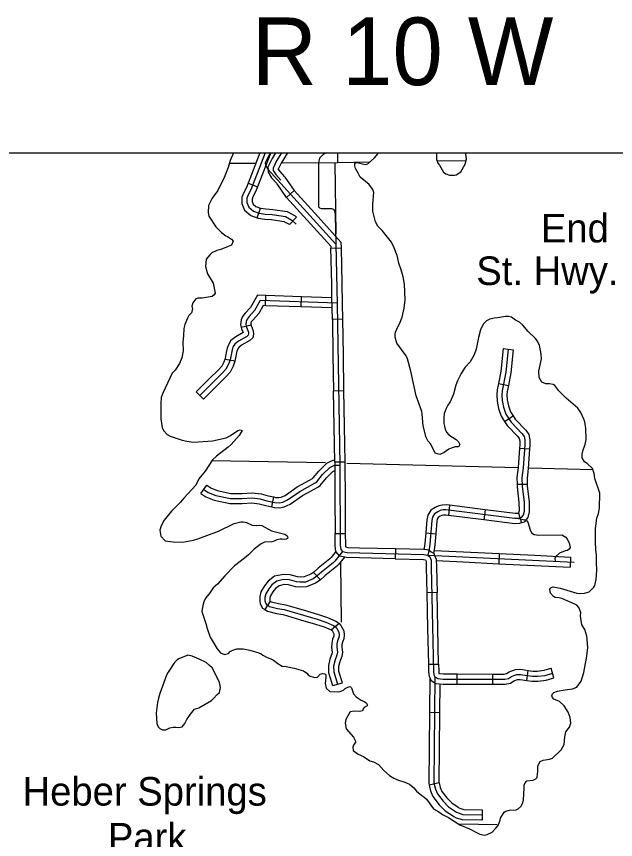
# Model space of a CAD drawing. Extents: x 1212896 to 1368412, y 378476 to 478763.
# Drawn here: x 1289419 to 1298275, y 427349 to 439519 of the extents above; entities that cross this region are included whole.
import ezdxf

# ---------------------------------------------------------------- set-up
doc = ezdxf.new("R2010")
doc.units = 0
for name, color, linetype in [('1', 7, 'Continuous'), ('Level 31', 7, 'Continuous'), ('Level 32', 7, 'Continuous'), ('Level 4', 7, 'Continuous'), ('Level 41', 7, 'Continuous'), ('Level 45', 7, 'Continuous'), ('Level 5', 7, 'Continuous'), ('Level 7', 7, 'Continuous'), ('Level 9', 7, 'Continuous'), ('R_Draft', 7, 'Continuous')]:
    doc.layers.add(name, color=color, linetype=linetype)

msp = doc.modelspace()

# ---------------------------------------------------------------- linework, layer by layer
at = {"layer": '1'}
msp.add_lwpolyline([(1257400, 437504), (1319317, 437504), (1319317, 388319), (1257400, 388319)], close=True, dxfattribs=at)
at = {"layer": 'Level 31'}
for p, q in [((1293175, 437493), (1293148, 437504)), ((1293288, 437261), (1293288, 437264)), ((1293524, 436945), (1293413, 436844)), ((1294067, 436095), (1294217, 436099)), ((1294086, 435209), (1294083, 435359)), ((1294239, 435043), (1294089, 435040)), ((1294106, 433984), (1294256, 433987)), ((1294274, 432931), (1294124, 432928)), ((1294130, 431873), (1294280, 431874)), ((1295020, 431651), (1295016, 431501)), ((1295636, 431000), (1295486, 430996)), ((1295508, 429941), (1295658, 429944))]:
    msp.add_line(p, q, dxfattribs=at)
for points in [[(1293248, 437504), (1293198, 437421), (1293137, 437292), (1293138, 437258)], [(1293181, 437504), (1293173, 437488)], [(1293424, 437504), (1293330, 437349), (1293288, 437261)], [(1293138, 437258), (1293139, 437216), (1293190, 437134), (1293270, 437047)], [(1293288, 437264), (1293288, 437261), (1293310, 437225), (1293381, 437147)], [(1293385, 437145), (1293524, 436945)], [(1293413, 436844), (1293273, 437043)], [(1293524, 436945), (1293879, 436554)], [(1293413, 436844), (1293768, 436453)], [(1293879, 436554), (1294216, 436182), (1294217, 436099)], [(1293768, 436453), (1294067, 436123), (1294067, 436095)], [(1294079, 435568), (1294067, 436095)], [(1294217, 436099), (1294229, 435571)], [(1294083, 435359), (1294079, 435568)], [(1294229, 435571), (1294235, 435270), (1294239, 435043)], [(1294089, 435040), (1294086, 435209)], [(1294089, 435040), (1294098, 434512)], [(1294239, 435043), (1294248, 434515)], [(1294098, 434512), (1294106, 433984)], [(1294248, 434515), (1294256, 433987)], [(1294115, 433456), (1294106, 433984)], [(1294256, 433987), (1294265, 433459)], [(1294124, 432928), (1294115, 433456)], [(1294265, 433459), (1294274, 432931)], [(1294124, 432928), (1294125, 432883), (1294127, 432401)], [(1294274, 432931), (1294275, 432884), (1294277, 432402)], [(1294127, 432401), (1294130, 431873)], [(1294277, 432402), (1294280, 431874)], [(1294488, 431514), (1294300, 431519), (1294201, 431541), (1294142, 431607), (1294131, 431698), (1294130, 431873)], [(1294280, 431874), (1294281, 431708), (1294285, 431676), (1294319, 431669), (1294492, 431664)], [(1294492, 431664), (1295020, 431651)], [(1295020, 431651), (1295443, 431641), (1295484, 431637), (1295521, 431627), (1295550, 431605), (1295583, 431583)], [(1295583, 431583), (1295593, 431570), (1295601, 431551)], [(1295601, 431551), (1295623, 431496), (1295628, 431378), (1295636, 431000)], [(1295016, 431501), (1294488, 431514)], [(1295016, 431501), (1295434, 431491), (1295466, 431486)], [(1295466, 431486), (1295475, 431464), (1295478, 431373), (1295486, 430996)], [(1295486, 430996), (1295497, 430469)], [(1295647, 430472), (1295636, 431000)], [(1295497, 430469), (1295508, 429941)], [(1295658, 429944), (1295647, 430472)]]:
    msp.add_lwpolyline(points, dxfattribs=at)
at = {"layer": 'Level 32'}
for p, q in [((1292844, 437056), (1292984, 437001)), ((1292977, 436543), (1293026, 436685)), ((1293456, 436441), (1293559, 436550)), ((1293101, 435242), (1293106, 435392)), ((1293628, 435224), (1293633, 435374)), ((1292887, 434957), (1292742, 434918)), ((1296615, 434608), (1296764, 434592)), ((1292650, 434421), (1292503, 434449)), ((1296544, 434091), (1296691, 434063)), ((1292184, 433862), (1292078, 433968)), ((1296636, 433532), (1296761, 433615)), ((1296855, 433134), (1297005, 433124)), ((1296819, 432602), (1296969, 432604)), ((1295823, 432291), (1295804, 432142)), ((1296347, 432224), (1296328, 432075)), ((1296839, 432174), (1296883, 432031)), ((1295469, 431883), (1295618, 431870)), ((1296963, 429702), (1296985, 429851)), ((1297364, 429739), (1297323, 429881)), ((1295934, 429647), (1295934, 429797)), ((1296462, 429646), (1296462, 429796))]:
    msp.add_line(p, q, dxfattribs=at)
for points in [[(1293098, 437504), (1292885, 436956), (1292845, 436884), (1292827, 436833), (1292826, 436767), (1292853, 436700), (1292921, 436640), (1293009, 436610), (1293097, 436597), (1293199, 436591), (1293395, 436560), (1293492, 436508), (1293555, 436449)], [(1293019, 437504), (1292844, 437056)], [(1293175, 437493), (1292984, 437001)], [(1293174, 437504), (1293149, 437464), (1293098, 437356), (1293099, 437319), (1293136, 437260), (1294140, 436152), (1294159, 435269), (1294198, 432884), (1294205, 431703), (1294213, 431639), (1294240, 431608), (1294309, 431593), (1295440, 431564), (1295498, 431556), (1295529, 431527), (1295548, 431480), (1295552, 431376), (1295584, 429837), (1295591, 429783), (1295606, 429754), (1295646, 429728), (1295729, 429721), (1296638, 429720), (1296693, 429731), (1296736, 429760), (1296811, 429788), (1296871, 429790), (1297046, 429764), (1297121, 429763), (1297235, 429777), (1297343, 429810)], [(1293338, 437504), (1293265, 437384), (1293214, 437276), (1293215, 437239), (1293251, 437181), (1293326, 437098)], [(1292844, 437056), (1292818, 436988), (1292778, 436915), (1292753, 436846), (1292752, 436753), (1292791, 436656), (1292883, 436575), (1292977, 436543)], [(1292984, 437001), (1292954, 436924), (1292915, 436853), (1292903, 436819), (1292902, 436781), (1292917, 436745), (1292960, 436707), (1293026, 436685)], [(1293026, 436685), (1293027, 436684), (1293104, 436674), (1293207, 436667), (1293420, 436633), (1293537, 436570), (1293559, 436550)], [(1292977, 436543), (1292991, 436538), (1293090, 436524), (1293191, 436518), (1293371, 436489), (1293449, 436448), (1293456, 436441)], [(1293024, 435318), (1292940, 435172), (1292859, 435082), (1292828, 435041), (1292813, 435011), (1292808, 434966), (1292819, 434926), (1292848, 434852), (1292850, 434828), (1292845, 434805), (1292826, 434789), (1292703, 434718), (1292648, 434675), (1292625, 434637), (1292606, 434591), (1292577, 434441), (1292555, 434376), (1292516, 434305), (1292464, 434248), (1292130, 433914)], [(1293106, 435392), (1292981, 435396), (1292878, 435217), (1292800, 435131), (1292762, 435081), (1292739, 435032), (1292731, 434960), (1292742, 434918)], [(1294159, 435280), (1293024, 435318)], [(1293633, 435374), (1293106, 435392)], [(1294083, 435359), (1293633, 435374)], [(1293101, 435242), (1293066, 435243), (1293000, 435128), (1292916, 435035), (1292891, 435003), (1292885, 434991), (1292883, 434971), (1292887, 434957)], [(1293628, 435224), (1293101, 435242)], [(1294086, 435209), (1293628, 435224)], [(1292887, 434957), (1292889, 434948), (1292920, 434870), (1292925, 434823), (1292911, 434765), (1292869, 434728), (1292745, 434657), (1292704, 434625), (1292691, 434604), (1292677, 434569), (1292667, 434520)], [(1292742, 434918), (1292746, 434902), (1292769, 434844), (1292661, 434781), (1292590, 434727), (1292557, 434672), (1292532, 434613), (1292520, 434548)], [(1296688, 434600), (1296651, 434260), (1296599, 433986), (1296592, 433925), (1296598, 433842), (1296618, 433741), (1296652, 433640), (1296733, 433518), (1296889, 433355), (1296922, 433308), (1296932, 433253), (1296932, 433184), (1296910, 432843), (1296892, 432698), (1296893, 432571), (1296922, 432337), (1296924, 432201), (1296911, 432146), (1296880, 432110), (1296840, 432097), (1296787, 432094), (1295768, 432223), (1295723, 432222), (1295685, 432214), (1295647, 432197), (1295599, 432164), (1295568, 432117), (1295558, 432067), (1295529, 431716), (1295519, 431645), (1295498, 431556)], [(1296615, 434608), (1296578, 434271), (1296544, 434091)], [(1296764, 434592), (1296727, 434249), (1296691, 434063)], [(1292520, 434548), (1292503, 434460), (1292485, 434407), (1292453, 434350), (1292409, 434300), (1292264, 434156)], [(1292667, 434520), (1292648, 434422), (1292623, 434346), (1292576, 434262), (1292517, 434197), (1292370, 434050)], [(1292264, 434156), (1292076, 433968)], [(1296544, 434091), (1296526, 433997), (1296519, 433926), (1296525, 433832), (1296547, 433722), (1296585, 433608), (1296636, 433532)], [(1292370, 434050), (1292182, 433862)], [(1296691, 434063), (1296675, 433975), (1296669, 433923), (1296674, 433852), (1296692, 433761), (1296721, 433674), (1296761, 433615)], [(1296761, 433615), (1296793, 433566), (1296948, 433404), (1296994, 433339), (1297008, 433259), (1297008, 433182), (1297005, 433124)], [(1296636, 433532), (1296675, 433472), (1296832, 433308), (1296852, 433279), (1296858, 433246), (1296858, 433186), (1296855, 433134)], [(1296855, 433134), (1296837, 432850), (1296818, 432702), (1296819, 432602)], [(1297005, 433124), (1296986, 432836), (1296968, 432694), (1296969, 432604)], [(1296819, 432602), (1296820, 432566), (1296848, 432333), (1296850, 432209), (1296843, 432180), (1296838, 432174)], [(1296969, 432604), (1296970, 432576), (1296998, 432343), (1297000, 432193), (1296981, 432110), (1296924, 432043), (1296883, 432031)], [(1295823, 432291), (1295771, 432297), (1295714, 432295), (1295662, 432284), (1295611, 432261), (1295546, 432217), (1295499, 432146), (1295485, 432077), (1295469, 431883)], [(1296347, 432224), (1295823, 432291)], [(1295804, 432142), (1295764, 432147), (1295732, 432145), (1295708, 432141), (1295685, 432130), (1295654, 432109), (1295640, 432087), (1295634, 432056), (1295618, 431870)], [(1296328, 432075), (1295804, 432142)], [(1296839, 432174), (1296827, 432170), (1296789, 432168), (1296347, 432224)], [(1296883, 432031), (1296853, 432021), (1296784, 432017), (1296328, 432075)], [(1295469, 431883), (1295456, 431724), (1295447, 431658), (1295443, 431641)], [(1295618, 431870), (1295605, 431708), (1295595, 431631), (1295583, 431583)], [(1295508, 429941), (1295511, 429832), (1295520, 429762), (1295549, 429703), (1295621, 429656), (1295725, 429647), (1295934, 429647)], [(1295658, 429944), (1295661, 429843), (1295665, 429806), (1295671, 429802), (1295732, 429797), (1295934, 429797)], [(1296462, 429796), (1296631, 429796), (1296663, 429803), (1296701, 429828), (1296796, 429864), (1296876, 429867), (1296985, 429851)], [(1296985, 429851), (1297052, 429841), (1297117, 429840), (1297219, 429852), (1297321, 429883)], [(1295934, 429797), (1296462, 429796)], [(1296462, 429646), (1296645, 429646), (1296722, 429662), (1296770, 429694), (1296826, 429715), (1296867, 429716), (1296963, 429702)], [(1296963, 429702), (1297040, 429691), (1297125, 429690), (1297250, 429704), (1297365, 429740)], [(1295934, 429647), (1296462, 429646)]]:
    msp.add_lwpolyline(points, dxfattribs=at)
at = {"layer": 'Level 4'}
for points in [[(1296065, 437386), (1295641, 437379)], [(1292956, 437347), (1292566, 437346)], [(1294637, 437363), (1294172, 437356), (1293348, 437348)]]:
    msp.add_lwpolyline(points, dxfattribs=at)
at = {"layer": 'Level 45'}
for p, q in [((1292145, 432467), (1292231, 432590)), ((1293193, 432268), (1293225, 432414)), ((1296556, 431578), (1296549, 431428)), ((1297611, 431526), (1297604, 431376)), ((1293913, 431188), (1293811, 431298)), ((1293171, 430876), (1293089, 430751)), ((1294190, 430544), (1294074, 430449)), ((1294235, 429659), (1294092, 429622)), ((1295674, 429225), (1295524, 429227)), ((1295666, 428188), (1295520, 428153)), ((1296305, 427788), (1296302, 427638))]:
    msp.add_line(p, q, dxfattribs=at)
for points in [[(1293999, 437504), (1293954, 437477), (1293901, 437425), (1293882, 437353), (1293884, 436735), (1293886, 436705), (1293900, 436688), (1293923, 436678), (1294074, 436679), (1294104, 436669), (1294125, 436634), (1294130, 436578), (1294140, 436152)], [(1292187, 432527), (1292254, 432480), (1292364, 432437), (1292581, 432391), (1292752, 432392), (1292901, 432401), (1293021, 432388), (1293121, 432359), (1293240, 432333), (1293302, 432329), (1293356, 432339), (1293428, 432370), (1293607, 432497), (1293837, 432623), (1293859, 432639), (1293945, 432746), (1294051, 432850), (1294119, 432885), (1294198, 432884)], [(1293641, 432603), (1293796, 432687), (1293806, 432695), (1293888, 432798), (1294006, 432912), (1294046, 432933)], [(1294046, 432933), (1294100, 432961), (1294123, 432961)], [(1293713, 432471), (1293876, 432560), (1293910, 432585), (1294000, 432697), (1294095, 432789), (1294115, 432800)], [(1294115, 432800), (1294125, 432805)], [(1292231, 432590), (1292291, 432548), (1292386, 432510), (1292589, 432468), (1292687, 432468)], [(1293225, 432414), (1293250, 432409), (1293297, 432406), (1293334, 432412), (1293390, 432437), (1293567, 432562), (1293641, 432603)], [(1292145, 432467), (1292219, 432415), (1292343, 432366), (1292573, 432318), (1292688, 432318)], [(1292687, 432468), (1292749, 432468), (1292903, 432478), (1293036, 432463), (1293140, 432433), (1293225, 432414)], [(1293193, 432268), (1293230, 432260), (1293306, 432255), (1293377, 432268), (1293464, 432306), (1293646, 432434), (1293713, 432471)], [(1292688, 432318), (1292754, 432318), (1292899, 432327), (1293006, 432315), (1293103, 432287), (1293193, 432268)], [(1296840, 432097), (1296936, 432078), (1296965, 432062), (1296978, 432044), (1297012, 431927), (1297033, 431885), (1297070, 431861), (1297142, 431850), (1297480, 431857), (1297540, 431820), (1297562, 431791), (1297589, 431737), (1297606, 431665), (1297590, 431642), (1297563, 431625), (1297532, 431617), (1297449, 431585), (1297396, 431540), (1297379, 431512), (1297381, 431463)], [(1294240, 431608), (1294127, 431467), (1294101, 431441), (1293930, 431304), (1293861, 431241), (1293806, 431205), (1293690, 431157), (1293607, 431154), (1293558, 431161), (1293453, 431187), (1293368, 431193), (1293269, 431170), (1293196, 431113), (1293149, 431055), (1293106, 430980), (1293093, 430930), (1293092, 430884), (1293096, 430860), (1293115, 430825), (1293159, 430796), (1293278, 430767), (1293377, 430750), (1293863, 430608), (1293993, 430565), (1294106, 430515), (1294132, 430499), (1294154, 430471), (1294184, 430414), (1294188, 430369), (1294185, 430336), (1294166, 430289), (1294157, 430244), (1294154, 430193), (1294163, 430119), (1294156, 430075), (1294129, 430006), (1294106, 429915), (1294109, 429829), (1294164, 429648)], [(1294142, 431607), (1294071, 431518), (1294051, 431499), (1293880, 431362), (1293811, 431298)], [(1295498, 431556), (1297666, 431449)], [(1295594, 431625), (1296029, 431604)], [(1296029, 431604), (1296556, 431578)], [(1296556, 431578), (1297084, 431552)], [(1297084, 431552), (1297611, 431526)], [(1294269, 431526), (1294182, 431417), (1294150, 431386), (1293978, 431249), (1293913, 431188)], [(1295624, 431473), (1296022, 431454)], [(1296022, 431454), (1296549, 431428)], [(1296549, 431428), (1297076, 431402)], [(1293814, 431301), (1293770, 431273), (1293673, 431233), (1293611, 431230), (1293573, 431236), (1293466, 431262), (1293362, 431270), (1293342, 431265)], [(1297076, 431402), (1297604, 431376)], [(1293342, 431265), (1293235, 431241), (1293142, 431168), (1293086, 431099), (1293034, 431010), (1293016, 430941), (1293015, 430877), (1293023, 430834), (1293057, 430771), (1293089, 430751)], [(1293913, 431188), (1293907, 431183), (1293840, 431139), (1293706, 431084), (1293603, 431080), (1293544, 431088), (1293442, 431114), (1293374, 431119)], [(1293376, 431119), (1293301, 431102), (1293248, 431061), (1293210, 431013), (1293174, 430952), (1293166, 430920), (1293165, 430890), (1293166, 430885), (1293171, 430876)], [(1293171, 430876), (1293189, 430865), (1293293, 430839), (1293394, 430822), (1293658, 430744)], [(1293089, 430751), (1293128, 430725), (1293262, 430692), (1293360, 430675), (1293616, 430600)], [(1293658, 430744), (1293885, 430678), (1294019, 430634), (1294142, 430580), (1294182, 430554), (1294190, 430544)], [(1293616, 430600), (1293840, 430535), (1293966, 430493), (1294070, 430448), (1294080, 430441)], [(1294074, 430449), (1294090, 430429), (1294110, 430392), (1294112, 430369), (1294110, 430354), (1294093, 430311), (1294081, 430253), (1294077, 430191), (1294086, 430120), (1294082, 430096), (1294056, 430030), (1294052, 430014)], [(1294190, 430544), (1294216, 430512), (1294257, 430435), (1294262, 430369), (1294258, 430318), (1294237, 430267), (1294230, 430234), (1294228, 430196), (1294238, 430118), (1294228, 430056), (1294199, 429984), (1294198, 429979)], [(1294052, 430014), (1294030, 429923), (1294033, 429817), (1294091, 429626)], [(1294198, 429979), (1294180, 429908), (1294182, 429841), (1294234, 429669)], [(1295529, 429743), (1295524, 429227)], [(1295606, 429754), (1295590, 428190), (1295613, 428095), (1295642, 428025), (1295725, 427916), (1295808, 427835), (1295923, 427755), (1295949, 427742), (1296020, 427722), (1296303, 427716)], [(1295678, 429651), (1295674, 429225)], [(1295524, 429227), (1295519, 428699)], [(1295674, 429225), (1295669, 428697)], [(1295519, 428699), (1295514, 428182), (1295520, 428153)], [(1295669, 428697), (1295664, 428199), (1295666, 428188)], [(1295520, 428153), (1295540, 428071), (1295576, 427986), (1295667, 427865), (1295759, 427776), (1295864, 427703)], [(1295666, 428188), (1295683, 428118), (1295707, 428062), (1295780, 427965), (1295855, 427892), (1295949, 427826)], [(1295949, 427826), (1295961, 427818), (1295975, 427811), (1296031, 427796), (1296305, 427790)], [(1295864, 427703), (1295884, 427689), (1295921, 427670), (1296009, 427646), (1296301, 427640)]]:
    msp.add_lwpolyline(points, dxfattribs=at)
at = {"layer": 'Level 5'}
for points in [[(1294172, 437356), (1294170, 437504)], [(1294125, 437355), (1294139, 436305)], [(1293986, 432917), (1292304, 432949)], [(1296837, 432846), (1294304, 432910)], [(1297940, 432818), (1296997, 432842)], [(1294207, 431443), (1294220, 430564)], [(1296523, 427565), (1295972, 427576)]]:
    msp.add_lwpolyline(points, dxfattribs=at)
at = {"layer": 'Level 9'}
for points in [[(1292628, 437504), (1292576, 437387), (1292551, 437286), (1292490, 437139)], [(1295738, 433591), (1295738, 433499), (1295745, 433461), (1295757, 433418), (1295778, 433375), (1295812, 433332), (1295919, 433263), (1295955, 433229), (1295971, 433190), (1295958, 433160), (1295951, 433155), (1295905, 433157), (1295862, 433143), (1295812, 433121), (1295742, 433071), (1295676, 433044), (1295608, 433063), (1295543, 433195), (1295499, 433242), (1295475, 433295), (1295429, 433465), (1295418, 433639), (1295411, 433679), (1295326, 433912), (1295249, 434275), (1295202, 434456), (1295182, 434501), (1295041, 434688), (1295018, 434775), (1295017, 434819), (1295024, 434852), (1295040, 434894), (1295092, 434997), (1295122, 435074), (1295152, 435206), (1295163, 435327), (1295155, 435562), (1295135, 435668), (1295107, 435774), (1295074, 435870), (1295045, 435985), (1295001, 436096), (1294961, 436184), (1294905, 436258), (1294824, 436352), (1294759, 436418), (1294726, 436482), (1294685, 436641), (1294687, 436749), (1294704, 436915), (1294689, 436961), (1294633, 437032), (1294499, 437143), (1294472, 437201), (1294431, 437272), (1294419, 437311), (1294422, 437348), (1294455, 437358), (1294573, 437329), (1294611, 437339), (1294711, 437430), (1294766, 437495), (1294778, 437504)], [(1295629, 437504), (1295629, 437499), (1295627, 437441), (1295630, 437409), (1295647, 437352), (1295673, 437321), (1295734, 437219), (1295767, 437192), (1295821, 437170), (1295896, 437170), (1295919, 437179), (1295988, 437224), (1296054, 437336), (1296070, 437407), (1296062, 437493), (1296057, 437504)], [(1292490, 437139), (1292395, 436946), (1292314, 436832), (1292260, 436725), (1292252, 436621), (1292263, 436567), (1292367, 436408), (1292452, 436325), (1292513, 436276), (1292537, 436267), (1292600, 436225), (1292621, 436198), (1292600, 436136), (1292551, 436116)], [(1292551, 436116), (1292441, 436073), (1292382, 436057), (1292306, 436022), (1292283, 436001), (1292223, 435931), (1292213, 435821), (1292242, 435714), (1292325, 435576), (1292355, 435427), (1292344, 435401), (1292311, 435378), (1292162, 435356), (1292102, 435354), (1292072, 435342), (1292025, 435284), (1292012, 435236), (1292019, 435190), (1292006, 435138), (1291969, 435096), (1291948, 435059), (1291907, 434962), (1291895, 434907), (1291890, 434795), (1291878, 434704), (1291884, 434577), (1291866, 434474), (1291830, 434390), (1291764, 434288), (1291723, 434243), (1291585, 433950), (1291560, 433884), (1291552, 433798), (1291552, 433626), (1291555, 433571), (1291574, 433441), (1291592, 433397), (1291646, 433340), (1291689, 433313), (1291867, 433253), (1291936, 433240), (1292035, 433224), (1292315, 433242), (1292520, 433291), (1292583, 433322), (1292693, 433397), (1292726, 433406), (1292757, 433395), (1292712, 433325), (1292593, 433191), (1292548, 433149), (1292375, 433020), (1292318, 432963), (1292209, 432797), (1292117, 432682), (1292072, 432590), (1291892, 432398)], [(1297816, 430992), (1297884, 431014), (1297953, 431080), (1297969, 431105), (1297989, 431192), (1297998, 431331), (1297992, 431452), (1297995, 431557), (1297983, 431628), (1297977, 431755), (1297977, 431947), (1297998, 432101), (1298023, 432172), (1298036, 432248), (1298042, 432473), (1297971, 432686), (1297958, 432761), (1297934, 432836), (1297854, 432909), (1297815, 432936), (1297782, 432994), (1297783, 433049), (1297797, 433112), (1297826, 433192), (1297840, 433265), (1297836, 433427), (1297819, 433523), (1297805, 433566), (1297760, 433661), (1297720, 433725), (1297546, 433874), (1297435, 433983), (1297376, 434061), (1297351, 434075), (1297300, 434085), (1297243, 434087), (1297185, 434114), (1297146, 434182), (1297141, 434273), (1297179, 434458), (1297176, 434527), (1297152, 434661), (1297116, 434725), (1297090, 434759), (1296984, 434859), (1296907, 434954), (1296857, 435000), (1296797, 435029), (1296737, 435071), (1296694, 435084), (1296649, 435085), (1296529, 435063), (1296481, 435060), (1296416, 435042), (1296369, 435021), (1296318, 434968), (1296281, 434885), (1296251, 434773), (1296214, 434598), (1296187, 434516), (1296128, 434412), (1296053, 434335), (1295995, 434240), (1295939, 434130), (1295915, 434067), (1295882, 433933), (1295831, 433821), (1295798, 433774), (1295766, 433714), (1295741, 433648), (1295738, 433591)], [(1291892, 432398), (1291843, 432338), (1291709, 432203), (1291604, 432073), (1291558, 431988), (1291539, 431925), (1291553, 431835), (1291618, 431765), (1291735, 431749), (1291874, 431747), (1292037, 431775), (1292099, 431794), (1292408, 431908), (1292639, 432020), (1292736, 432048), (1292772, 432048), (1292822, 432035), (1292905, 431996), (1292969, 431994), (1293012, 431997), (1293045, 431992), (1293189, 431916), (1293387, 431865), (1293423, 431839), (1293430, 431822), (1293424, 431798), (1293410, 431789), (1293381, 431786), (1293345, 431791), (1293317, 431790), (1293269, 431780), (1293230, 431762), (1293193, 431751), (1293087, 431747), (1293035, 431721), (1292996, 431693), (1292931, 431644), (1292847, 431560), (1292788, 431508), (1292641, 431398), (1292501, 431250), (1292393, 431126), (1292329, 431069), (1292269, 430983), (1292215, 430918), (1292191, 430864), (1292180, 430829), (1292163, 430756), (1292161, 430723), (1292218, 430546), (1292236, 430468), (1292282, 430340), (1292387, 430171), (1292433, 430109), (1292496, 430085), (1292554, 430100), (1292580, 430129), (1292619, 430148), (1292679, 430169), (1292768, 430169), (1292869, 430148), (1293003, 430110), (1293035, 430096), (1293060, 430074), (1293123, 430041), (1293179, 430023), (1293220, 430003), (1293283, 429953), (1293349, 429915), (1293406, 429908), (1293525, 429883), (1293663, 429842), (1293712, 429811), (1293731, 429786), (1293760, 429765), (1293832, 429743), (1293868, 429752), (1293910, 429793)], [(1296504, 427516), (1296541, 427557), (1296570, 427638), (1296574, 427665), (1296631, 427752), (1296652, 427767), (1296708, 427785), (1296804, 427789), (1296838, 427801), (1296880, 427844), (1296906, 427893), (1296913, 427938), (1296925, 428108), (1296922, 428151), (1296940, 428190), (1296965, 428215), (1297059, 428227), (1297098, 428247), (1297118, 428269), (1297120, 428325), (1297126, 428346), (1297127, 428437), (1297163, 428501), (1297205, 428524), (1297299, 428539), (1297344, 428554), (1297473, 428676), (1297518, 428757), (1297526, 428868), (1297538, 428940), (1297595, 429013), (1297613, 429070), (1297605, 429154), (1297576, 429232), (1297518, 429325), (1297446, 429388), (1297363, 429427), (1297345, 429448), (1297332, 429476), (1297341, 429504), (1297364, 429525), (1297418, 429541), (1297531, 429564), (1297639, 429576), (1297701, 429600), (1297765, 429690), (1297805, 429821), (1297846, 430030), (1297865, 430184), (1297857, 430312), (1297850, 430357), (1297820, 430455), (1297779, 430524), (1297757, 430658), (1297762, 430706), (1297734, 430780), (1297703, 430814), (1297672, 430830), (1297480, 430911), (1297443, 430924), (1297385, 430927), (1297356, 430942), (1297312, 430994), (1297302, 431045), (1297315, 431071), (1297354, 431087), (1297457, 431067), (1297701, 430994), (1297744, 430987), (1297816, 430992)], [(1291819, 430023), (1291793, 430007), (1291755, 429965), (1291661, 429822), (1291638, 429780), (1291539, 429509), (1291521, 429441), (1291506, 429374), (1291486, 429216), (1291495, 429063), (1291515, 429016), (1291538, 428992), (1291577, 428971), (1291626, 428973), (1291688, 429000), (1291735, 429011), (1291781, 429011), (1291821, 429004), (1291867, 429015), (1291909, 429064), (1291940, 429123), (1291992, 429204), (1292053, 429275), (1292116, 429299), (1292302, 429406), (1292334, 429434), (1292386, 429492), (1292422, 429525), (1292433, 429599), (1292421, 429672), (1292366, 429786), (1292310, 429887), (1292275, 429924), (1292221, 429965), (1292120, 430015), (1292017, 430059), (1291951, 430074), (1291819, 430023)], [(1293910, 429793), (1293942, 429806), (1293976, 429799), (1293990, 429787), (1293992, 429748), (1293982, 429655), (1293999, 429588), (1294054, 429537), (1294171, 429532), (1294206, 429539), (1294255, 429558), (1294279, 429581), (1294310, 429599), (1294341, 429610), (1294357, 429605), (1294373, 429591), (1294401, 429502), (1294440, 429458), (1294515, 429411), (1294571, 429385), (1294595, 429364), (1294607, 429338), (1294602, 429327), (1294560, 429300), (1294545, 429280), (1294533, 429254), (1294486, 429244), (1294412, 429245), (1294358, 429237), (1294349, 429232), (1294288, 429126), (1294279, 429069), (1294293, 428984), (1294400, 428861), (1294432, 428806), (1294431, 428787), (1294403, 428744), (1294393, 428713), (1294396, 428666), (1294470, 428614), (1294550, 428579), (1294642, 428514), (1294697, 428496), (1294770, 428458), (1294852, 428371), (1294936, 428298), (1294997, 428257), (1295052, 428233), (1295158, 428200), (1295227, 428168), (1295293, 428115), (1295331, 428066), (1295412, 428003), (1295440, 427982), (1295479, 427946), (1295584, 427805), (1295664, 427760), (1295718, 427719), (1295805, 427676), (1295890, 427622), (1295972, 427566), (1296115, 427510), (1296229, 427448), (1296268, 427429), (1296339, 427415), (1296376, 427422), (1296453, 427460), (1296504, 427516)]]:
    msp.add_lwpolyline(points, dxfattribs=at)

# ---------------------------------------------------------------- texts
at = {"layer": 'Level 41'}
for s, p in [('End', (1297171, 436178)), ('St. Hwy.', (1296217, 435548))]:
    msp.add_text(s, height=422.4, dxfattribs=at).set_placement(p)
at = {"layer": 'Level 7'}
for s, p in [('Heber Springs', (1289509, 427851)), ('Park', (1290770, 427171))]:
    msp.add_text(s, height=422.4, dxfattribs=at).set_placement(p)
at = {"layer": 'R_Draft'}
msp.add_text('R 10 W', height=1000, dxfattribs=at).set_placement((1292897, 438504))

doc.saveas('drawing.dxf')
